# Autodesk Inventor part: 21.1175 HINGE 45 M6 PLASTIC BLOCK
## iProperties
Created: 2007-01
Part Number: 21.1175 HINGE 45 M6 PLASTIC BLOCK
Document SubType Name: Modeling
Designer: Andy Moles
Material: ABS Plastic
Mass: 8.32891 g
Surface Area: 44.691 cm^2
Volume: 7.85746 cm^3
Density: 1.06 g/cm^3
Author: Andy Moles
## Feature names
1. Base1
